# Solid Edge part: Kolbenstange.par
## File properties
Username: bmolnar
Dokumentum tartalom típus: 0
Author: bmolnar
Last saved by: bmolnar
Revision: 82
Sűrűség: 0,000 kg/m^3
Pontosság: 0,990
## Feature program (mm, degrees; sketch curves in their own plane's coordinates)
base feature "unnamed BaseFeature 1"
sketch for "unnamed Protrusion 1" plane through (30, 0, 0) normal (1, 0, 0) x-axis (0, -1, 0)
  circle centre (0, 0) radius 25
extrude "unnamed Protrusion 1" add finite 8.5 along +normal
sketch for "Kihúzás_2" plane through (30, 0, 0) normal (1, 0, 0) x-axis (0, -1, 0)
  circle centre (0, 0) radius 25
extrude "Kihúzás_2" add finite 7.5 along -normal
sketch for "Furat_2" plane through (-25, 0, 0) normal (-1, 0, 0) x-axis (0, 0, -1)
  hole centre (0, 0) bore radius 4.188
hole "Furat_2" nominal diameter 10 finite  ThreadDepth = 17 mm
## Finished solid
Body 1: solid body, 14 faces, 20 edges, 8 vertices.
  Faces by surface: plane 8, cylinder 4, cone 1, torus 1
  Edges by curve: circle 10, line 6, ellipse 2, intersection 2
Bounding box of the edges (mm; curved faces can reach further): 63.500 x 50.000 x 50.000, from (-25, -25, -25) to (38.5, 25, 25).
Cylindrical faces by radius (mm): R4.188 x2, R8 x1, R25 x1
Conical faces (half-angle, radius in mm at the cone's reference point): 45 deg R4.538 x1
Toroidal faces (ring radius, tube radius in mm): R6.3 r1.7 x1
Planar faces by outward normal: +x 1, +z 1, -x 3, -z 1, oblique 2
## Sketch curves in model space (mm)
circle centre (30, 0, 0) radius 25
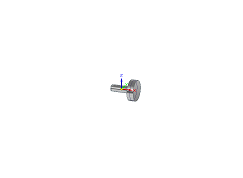
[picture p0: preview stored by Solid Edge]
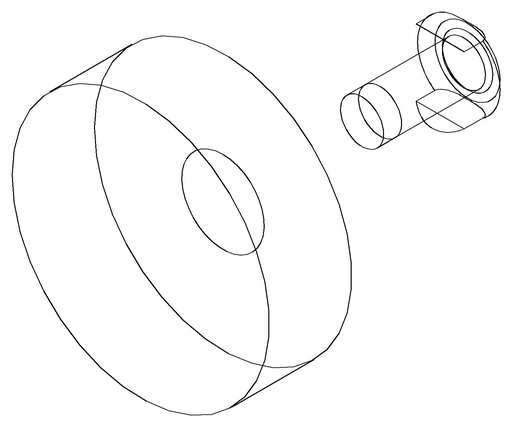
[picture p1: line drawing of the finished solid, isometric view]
